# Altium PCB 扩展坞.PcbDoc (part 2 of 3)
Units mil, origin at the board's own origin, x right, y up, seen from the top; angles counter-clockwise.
Board outline 3543.31 x 1968.5 mil, 4 copper layers (Top Layer 1, Layer1, Layer2, Bottom Layer 1), stack 62.337 mil thick; 191 components, 182 nets, 737 pads, 256 vias.
Unrouted connection lines stored in the file: 242.
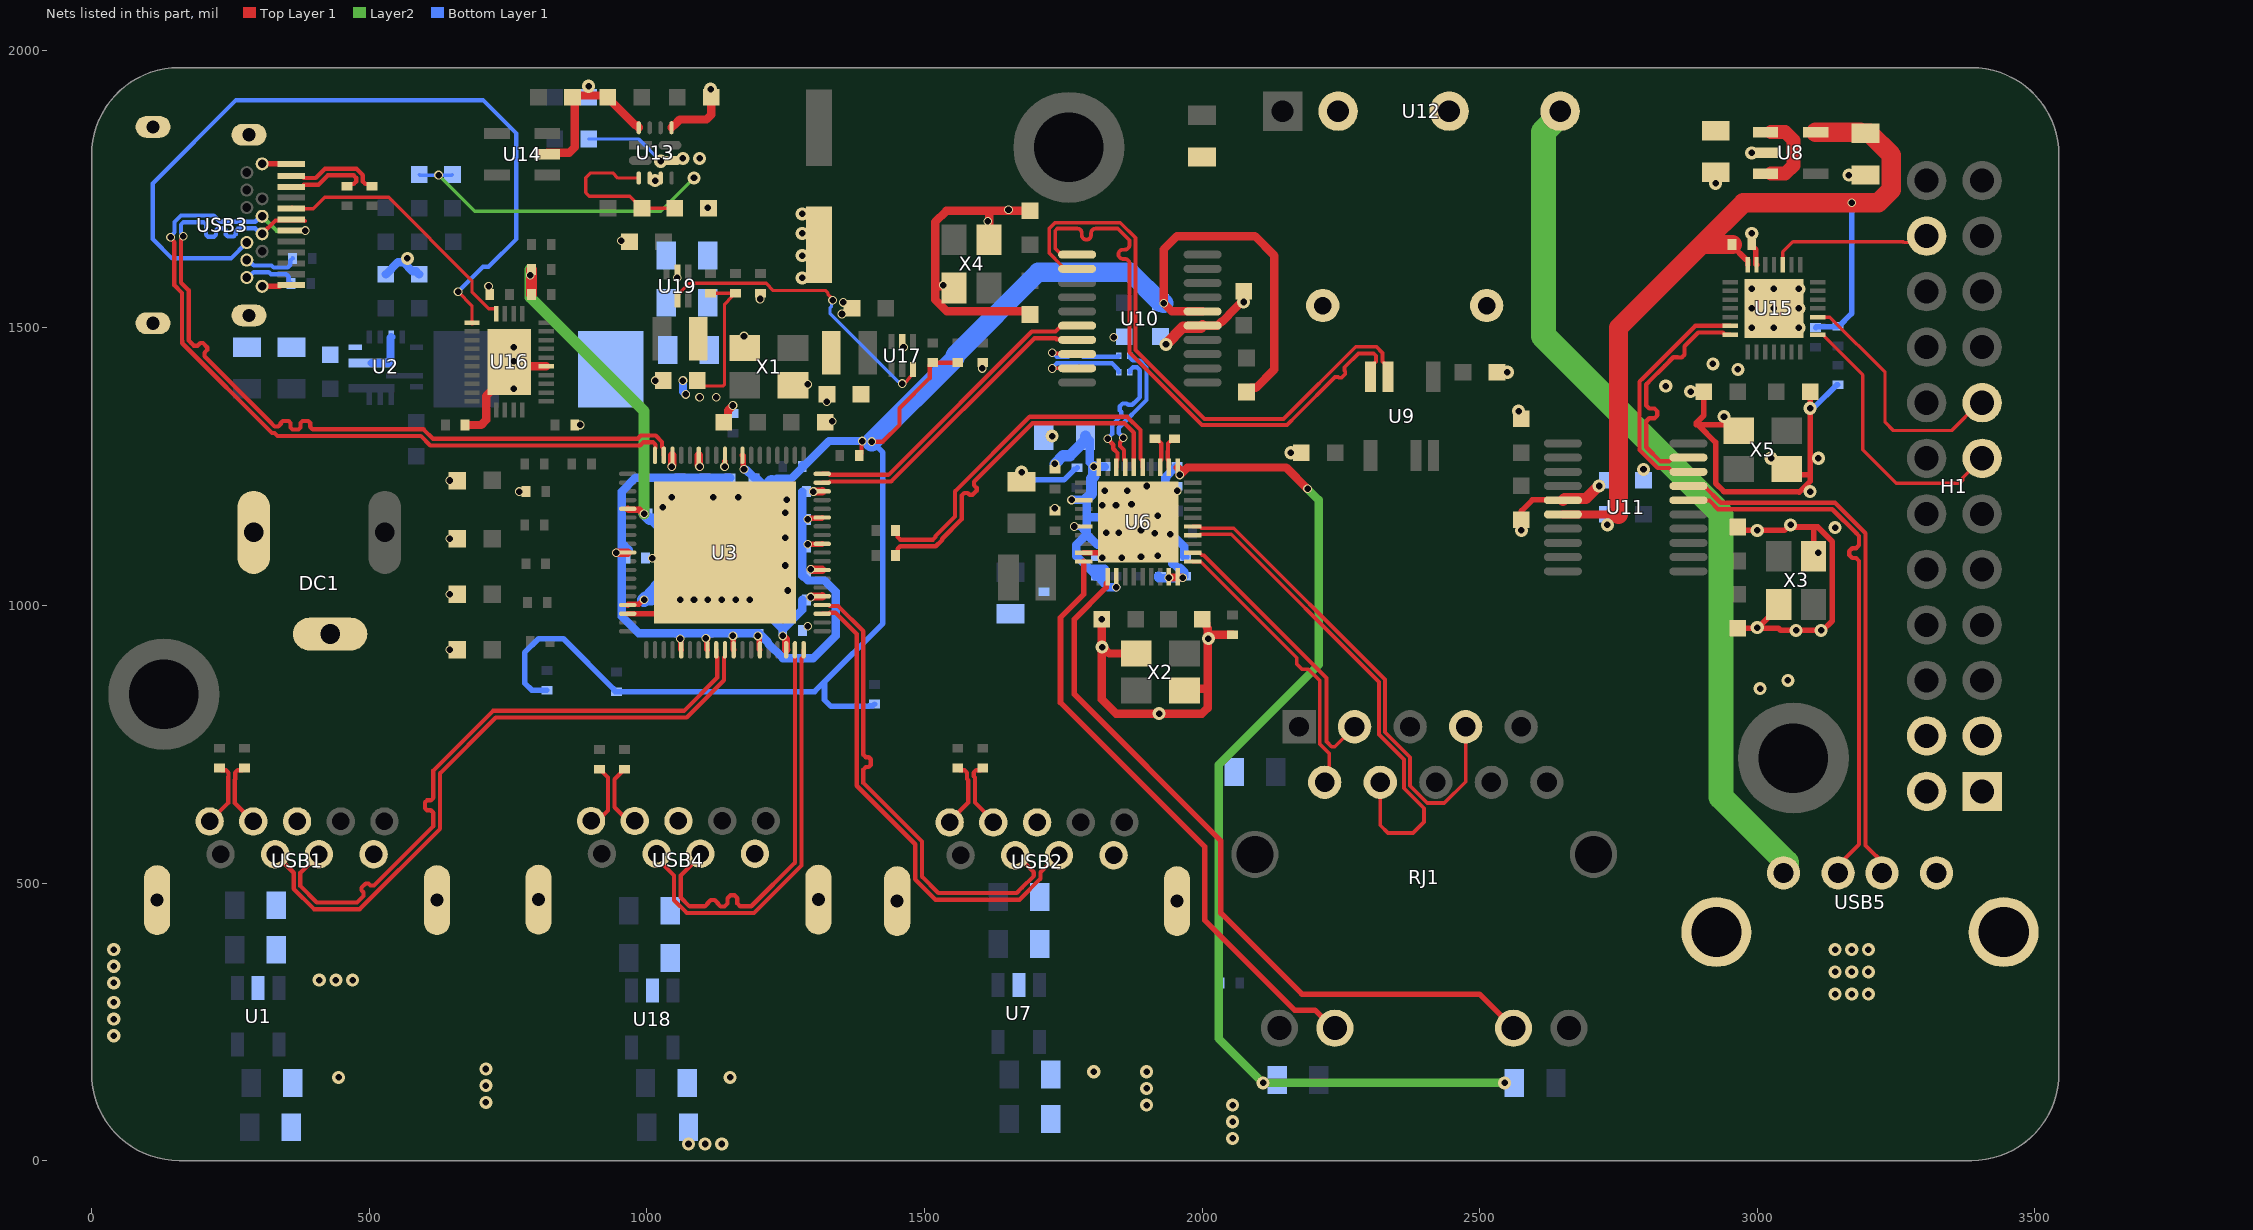
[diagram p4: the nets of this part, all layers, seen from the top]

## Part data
* *1 *2: "铜柱孔"
C1 C2 C3 C4 C5 C6 C7 C8 C9 C10 C11 C12 C13 C14 C15 C16 C17 C18 C19 C20 C21 C22 C23 C24 C25 C26 C27 C28 C29 C30 C31 C32 C33 C34 C35 C36 C38 C39 C40 C41 C42 C43 C44 C45 C46 C47 C48 C49 C50 C51 C52 C53 C54 C55 C56 C57 C58 C59 C60 C61 C62 C63 C64 C65 C66 C67 C68 C69 C70 C71 C72 C73 C74 C75 C76 C77 C78 C79 C80 C81 C82 C83 C84 C85 C87 C88 C89 C90 C91 C92 C93 C94 C95 C96 C97 C98 C99 C100 C101: library part C, "无极性贴片电容"
C37: "容值:220uF;精度:±20%;额定电压:25V;纹波电流:2.9A@100kHz;等效串联电阻(ESR):28mΩ@100kHz;类型:聚合物;", Equivalent Series Resistance(ESR)=28mΩ@100kHz, JLCPCB Part Class="Extended Part", LCSC Part Name="220uF ±20% 25V", Manufacturer=JIERR(捷而瑞), ManufacturerPart=MA25V220M6X8, Operating Temperature=-55℃~+105℃, Ripple Current=2.9A@100kHz, Tolerance=±20%, Voltage Rating=25V
C86: "容值:2.2nF;精度:±20%;工作电压(AC):300V;防护等级:Y2;", JLCPCB Part Class="Extended Part", LCSC Part Name="2.2nF ±20% 300V 等级:Y2", Manufacturer=QNR(勤宏科技), ManufacturerPart=Q222M060110FQ55250L7579, Operating Temperature=-40℃~+125℃, Ratings=Y2, Tolerance=±20%, Voltage(AC)=300V
DC1: "连接器类型:DC电源插座;安装方式:弯插;触点内径:2mm;触点外径:6.4mm;额定电流:3A;额定电压:30V;工作温度:-20℃~+70℃;", Current Rating=3A, JLCPCB Part Class="Extended Part", LCSC Part Name="DC电源插座 内径:2mm 外径:6.4mm", Manufacturer=XUNPU(讯普), ManufacturerPart=DC-005-A200, Operating Temperature=-20℃~+70℃, Voltage Rating (Max)=30V
H1: "插针结构:2x12P;间距:2.54mm;行距:2.54mm;圆针/方针:方针;排数:双排;总PIN位数:24P;额定电流:3A;额定电压:250V;配合针长度:-;塑高:2.5mm;端接针长度:-;触头材质:黄铜;触头镀层:金;工作温度:-40℃~+105℃;颜色:黑色;", Color=黑色, Current Rating=3A, JLCPCB Part Class="Extended Part", LCSC Part Name="2x12P 间距:2.54mm 方针", Manufacturer="XKB Connection(中国星坤)", ManufacturerPart=X6521WR-2x12H-C60D30, Operating Temperature=-40℃~+105℃, Voltage Rating (Max)=250V
L2: "合金电感 一体成型电感 大电流", JLCPCB Part Class="Extended Part", LCSC Part Name="3.3μH ±20% 9A", Manufacturer=JIERR(捷而瑞), ManufacturerPart=PCR0630-3R3-M
L3: "电感值:2.2uH;精度:±20%;额定电流:3A;饱和电流(Isat):3.8A;类型:磁胶屏蔽电感;", Current - Saturation(Isat)=3.8A, Current Rating=3A, DC Resistance(DCR)=55mΩ, JLCPCB Part Class="Extended Part", LCSC Part Name="2.2uH ±20% 3.8A", Manufacturer=SXN(顺翔诺), ManufacturerPart=SMMS252012-2R2M, Tolerance=±20%
LED1 LED2 LED3 LED4: "灯头类型:1.6mmx0.8mm方形灯头;发光颜色:翠绿色;正向压降(Vf):2.6V~2.9V;功率:90mW;正向电流:30mA;波长:520nm~525nm;二极管配置:独立二极管;透镜颜色:-;色温:-;发光强度:230mcd;发光角度:120°;载带方式:-;工作温度:-40℃~+85℃;", Color Temperature=-, Forward Current=30mA, Illumination Color=翠绿色, JLCPCB Part Class="Extended Part", LCSC Part Name=0603翠绿, Manufacturer=TUOZHAN(拓展光电), ManufacturerPart=F.0603.00025/P2-0603G1TS2-06T-002, Operating Temperature=-40℃~+85℃, Power(Watts)=90mW, Voltage - Forward(Vf)=2.6V~2.9V
R1 R2 R3 R4 R5 R6 R7 R8 R9 R10 R11 R12 R13 R14 R15 R16 R17 R18 R19 R20 R21 R22 R23 R24 R25 R26 R27 R28 R29 R30 R31 R32 R33 R34 R35 R36 R37 R38 R39 R40 R41 R42 R43 R44 R45 R46 R47 R48 R49: library part R, "贴片电阻"
RJ1: "连接器类型:RJ45插座;安装方式:弯插;端口数量:1;LED:带LED;屏蔽:有屏蔽;等级:-;触头材质:磷青铜;触头镀层:金;工作温度:0℃~+70℃;", JLCPCB Part Class="Extended Part", LCSC Part Name="弯插 带LED", Manufacturer=HANRUN(汉仁), ManufacturerPart=HR911130A, Operating Temperature=0℃~+70℃, Ratings=-
U1 U7 U18: "类型:负载开关;通道数:1;输入控制逻辑:高电平有效;工作电压:2.5V~5.5V;最大连续电流:2A;导通电阻:60mΩ;", JLCPCB Part Class="Extended Part", LCSC Part Name=低损耗功率分配开关, Manufacturer=Silergy(矽力杰), ManufacturerPart=SY6288CAAC, Maximum Continuous Current=2A, Operating Temperature	-=-40℃~+85℃, Voltage - Supply=2.5V~5.5V
U2: "功能类型:降压型;输出类型:可调;输入电压:4.5V~28V;输出电压:600mV~13V;输出电流(最大值):6A;", Input Voltage=4.5V~28V, JLCPCB Part Class="Extended Part", LCSC Part Name=TPS56637RPAR, Manufacturer=TI(德州仪器), Operating Temperature=-40℃~+150℃@(TJ), Output Current (Max)=6A, Output Voltage=600mV~13V, Switching Frequency=500kHz
U3: "VL822是一款USB 3.1 Gen2集线器控制器，具有高度集成的专用应用设计。VL822有1个上游端口和4个/2个下游端口，所有端口均支持10Gbps的USB 3.1 Gen2操作。下游端口可支持超速+（10Gbps）、超速（5Gbps）、高速（480Mbps）、全速（12Mbps）和低速（1.5Mbps）设备的任意组合", JLCPCB Part Class="Extended Part", LCSC Part Name="USB 3.1 Gen 2 集线器控制器", Manufacturer="VIA Labs(威锋电子)", ManufacturerPart=VL822-Q7, Voltage - Supply=0.95V~1.05V；3V~3.6V
U4 U5: "小型化一体成型T-CORE，小体积，扁线工艺，感值小", JLCPCB Part Class="Extended Part", LCSC Part Name="1uH ±20% 5.6A", Manufacturer=cjiang(长江微电), ManufacturerPart=FTC252012S1R0MBCA
U6: "类型:-;端口数量:1;MAC接口:-;", JLCPCB Part Class="Extended Part", LCSC Part Name="集成10/100/1000M以太网控制器用于USB 3.0应用", Manufacturer=REALTEK(瑞昱), ManufacturerPart=RTL8153B-VB-CG, Operating Temperature=0℃~+70℃, Power=-, Voltage - Supply=3.3V；1V；5V
U8: "输出极性:正极;工作电压:5.5V;输出电压:3.3V;输出电流:500mA;电源纹波抑制比(PSRR):50dB@(10kHz);输出类型:固定;", JLCPCB Part Class="Extended Part", LCSC Part Name="3.3V 500mA 5.5V", Manufacturer=RICHTEK(立锜), ManufacturerPart=RT9013-33GB, Operating Temperature=-40℃~+125℃@(Tj), Output Current=500mA, Output Voltage=3.3V, Power Supply Rejection Ratio (PSRR)=50dB@(10kHz), standby current=25uA, Voltage - Supply=5.5V, Voltage Dropout=400mV@(500mA)
U9: "线路数:4;电感@频率:120uH@100kHz;阻抗@频率:-;直流电阻(DCR):1.2Ω;", Current Rating=720mA, DC Resistance(DCR)=1.2Ω, Impedance @ Frequency=-, Inductance @ Frequency=120uH@100kHz, JLCPCB Part Class="Extended Part", LCSC Part Name="1G 30W 分离式变压器", Manufacturer=CND-tek(磁联达), ManufacturerPart=GA021G00, Operating Temperature=-40℃~+85℃, Voltage Withstand=1.5kV
U10 U11: "是高速USB信号隔离和传输距离延长控制芯片，支持电容耦合或者网络变压器耦合，不但实现了对USB信号的隔离，同时实现了对USB信号的实时中转和传输距离延长。此外，芯片自身带有USBHUB功能，上行端口支持USB2.0高速，下行端口支持USB2.0高速480Mbps、全速12Mbps和低速1.5Mbps。可以用于高速USB信号隔离、隔离HUB、延长HUB等。", Isolation Voltage(Vrms)=-, JLCPCB Part Class="Extended Part", LCSC Part Name=CH318T, Manufacturer=WCH(南京沁恒), Operating Temperature=-40℃~+85℃, Voltage - Supply=3.3V
U12: "DC-DC隔离电源模块:输入5V(4.5V~5.5V)@@输出5V 400mA 2W@@输出短路保护@@输入输出隔离耐压1.5KV@@SIP7", Capacitive Load(Max)=2400uF, Isolation Voltage(Vrms)=1.5kV, JLCPCB Part Class="Extended Part", LCSC Part Name="4.5V~5.5V 5V 400mA 2W", Manufacturer=EVISUN(易成), ManufacturerPart=B0505S-2WR3, Operating Temperature=-40℃~+105℃, Output Current(Max)=400mA, Output Power=2W, Output Voltage=5V, Quiescent Supply Current=8mA, Voltage - Supply=4.5V~5.5V, Voltage Regulation=非稳压型
U13: "TPS2121 支持无缝切换的 2.7V 至 22V、56mΩ、4.5A 电源多路复用器", JLCPCB Part Class="Extended Part", LCSC Part Name=TPS2121RUXR, Manufacturer=TI(德州仪器)
U14: "类型:高侧开关;通道数:1;输入控制逻辑:高电平有效;工作电压:2.4V~5.5V;最大连续电流:2A;导通电阻:80mΩ;", JLCPCB Part Class="Extended Part", LCSC Part Name=低损耗功率分配开关, Manufacturer=Silergy(矽力杰), ManufacturerPart=SY6280AAC, Maximum Continuous Current=2A, Operating Temperature	-=-40℃~+125℃, Voltage - Supply=2.4V~5.5V
U15: "应用功能:USB转UART；USB转SPI；USB转SWD；USB转I2C；USB转JTAG;USB协议版本:USB 2.0;通道数:2;数据速率:480Mbps;", Current - Supply=38mA, JLCPCB Part Class="Extended Part", LCSC Part Name="高速 USB 转换芯片", Manufacturer=WCH(南京沁恒), ManufacturerPart=CH347F, Operating Temperature=-, Quiescent Supply Current=260uA, Voltage - Supply=3V~3.6V
U16: "特性：USB Type-C数据开关，带适用于USB 3.1 Gen2 (10 Gbps)的CC功能。 4:2 10Gbps USB Type-C数据开关。 支持高达10Gbps。应用：线缆+设备应用", Current - Supply=1.2mA, JLCPCB Part Class="Extended Part", LCSC Part Name="支持CC功能的USB 3.1 Gen2 USB Type-C数据开关", Manufacturer="VIA Labs(威锋电子)", ManufacturerPart=VL162, Operating Temperature=-45℃~+85℃, Quiescent Supply Current=0.5mA, Voltage - Supply=4.5V~5.5V
U17 U19: "功能类型:降压型;工作电压:2.5V~5.5V;输出电压:600mV~5.5V;输出电流:3A;输出类型:可调;", Frequency - Switching=2MHz, JLCPCB Part Class="Extended Part", LCSC Part Name="降压型 3A 2.5V~5.5V", Manufacturer=ETA(钰泰), ManufacturerPart=ETA3512FSG, Operating Temperature=-40℃~+85℃@(TA), Output Current=3A, Output Voltage=600mV~5.5V, Quiescent Current=50uA, Voltage - Supply=2.5V~5.5V
USB1 USB2 USB4: "连接器类型:Type-A;协议标准:USB 3.0;公母:母;安装方式:弯插;触点数量:9P;端口数量:1;额定电流 - 电源:1.5A;工作温度:-25℃~+70℃;", Current Rating-Power=1.5A, Detection color=蓝色, JLCPCB Part Class="Extended Part", LCSC Part Name="Type-A 母 弯插 USB3.0 AF90度 直脚蓝胶卷边 吸塑盒", Manufacturer=HC(虹成电子), ManufacturerPart=HC-USB3.0-L168-ZJ, Operating Temperature=-25℃~+70℃, Voltage Rating=30V
USB3: "连接器类型:Type-C;协议标准:USB 3.1;公母:母;安装方式:卧贴;触点数量:24P;端口数量:1;额定电流 - 电源:3A;工作温度:-40℃~+85℃;", Current Rating-Power=3A, Detection color=黑色, JLCPCB Part Class="Extended Part", LCSC Part Name=24P卧贴母座, Manufacturer="SHOU HAN(首韩)", ManufacturerPart="TYPE-C 24P QCHT", Operating Temperature=-40℃~+85℃, Voltage Rating=30V
USB5: "连接器类型:Type-A;协议标准:USB 2.0;公母:母;安装方式:弯插;触点数量:4P;端口数量:1;额定电流 - 电源:1.5A;工作温度:-25℃~+85℃;", Current Rating-Power=1.5A, Detection color=白色, JLCPCB Part Class="Extended Part", LCSC Part Name="Type-A 母 弯插", Manufacturer="SHOU HAN(首韩)", ManufacturerPart="AF 90° WJDG", Operating Temperature=-25℃~+85℃, Voltage Rating=30V
X1 X2: "晶振类型:贴片晶振;频率:25MHz;常温频差:±10ppm;负载电容:12pF;频率稳定度:±20ppm;", Equivalent Series Resistance(ESR)=50Ω, Frequency Stability=±20ppm, JLCPCB Part Class="Basic Part", LCSC Part Name="YSX321SL 25MHZ 4P 3225 12PF ±10PPM -40~85℃ (±20PPM)", Load Capacitance=12pF, Manufacturer=YXC(扬兴晶振), ManufacturerPart=X322525MOB4SI, Normal temperature Frequency Tolerance=±10ppm, Operating Temperature=-40℃~+85℃
X3 X4: "晶振类型:贴片晶振;频率:20MHz;常温频差:±10ppm;负载电容:20pF;频率稳定度:±20ppm;", Equivalent Series Resistance(ESR)=50Ω, Frequency Stability=±20ppm, JLCPCB Part Class="Extended Part", LCSC Part Name="YSX321SL 20MHZ 4P 3225 20PF ±10PPM -40~85℃ (±20PPM)", Load Capacitance=20pF, Manufacturer=YXC(扬兴晶振), ManufacturerPart=X322520MSB4SI, Normal temperature Frequency Tolerance=±10ppm, Operating Temperature=-40℃~+85℃
X5: "晶振类型:贴片晶振;频率:8MHz;常温频差:±10ppm;负载电容:12pF;频率稳定度:±20ppm;", Equivalent Series Resistance(ESR)=180Ω, Frequency Stability=±20ppm, JLCPCB Part Class="Extended Part", LCSC Part Name="YSX321SL 8MHZ 4P 3225 12PF ±10PPM -40~85℃ (±20PPM)", Load Capacitance=12pF, Manufacturer=YXC(扬兴晶振), ManufacturerPart=XL2EL89COI-111YLC-8M, Normal temperature Frequency Tolerance=±10ppm, Operating Temperature=-40℃~+85℃

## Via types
v1: diameter 15.75, hole 11.81, Top Layer 1 to Bottom Layer 1, tented both sides, 127 vias
v2: diameter 23.62, hole 11.81, Top Layer 1 to Bottom Layer 1, tented both sides, 118 vias
v3: diameter 15.75, hole 11.81, Top Layer 1 to Bottom Layer 1, 10 vias
v4: diameter 23.62, hole 11.81, Top Layer 1 to Bottom Layer 1, 1 vias

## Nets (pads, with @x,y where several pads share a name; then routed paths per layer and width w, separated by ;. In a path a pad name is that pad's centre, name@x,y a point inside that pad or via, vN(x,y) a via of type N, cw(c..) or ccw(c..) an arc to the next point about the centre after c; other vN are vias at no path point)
1V05_SYS: C1.2 C2.2 C5.2 C6.2 C7.2 C8.2 C10.2 C11.2 C12.2 C13.2 C75.2 C79.1 C80.2 C81.2 R9.1 U3.5 U3.8 U3.11 U3.14 U3.27 U3.30 U3.33 U3.36 U3.48 U3.51 U3.54 U3.67 U5.2 | length 1741.8
  Top Layer 1 w6: C75.2@1090.59,1405 1100.59,1395 1136.49,1395 1140,1398.51 1140,1542.28 1153.16,1555.44 1153.16,1557.41 C79.1@1158.03,1562.28 ; R9.1@1115,1562.28 C79.1@1158.03,1562.28 ; C79.1@1160,1562.28 C79.1@1158.03,1562.28
  Top Layer 1 w10: v1(1060,940) 1060,938.34 1061,937.34 1061,921 U3.5@1062,920 ; v1(1106.38,940.98) 1107.48,939.88 1107.48,936.72 1108.14,936.06 1108.14,921.06 U3.8@1109.2,920 ; v1(1140,1250) 1140.35,1250.35 U3.48@1140.35,1259.65 ; v1(1155,945) 1155.7,944.3 1155.7,920.7 U3.11@1156.4,920 ; v1(1200,945) 1200,943.44 1202.64,940.81 1202.64,921.06 U3.14@1203.7,920 ; v1(1290,1110) 1290.45,1110.45 1315.45,1110.45 U3.30@1315.9,1110.9 ; v1(1290,1155) 1291.56,1155 1293.69,1157.14 1314.84,1157.14 U3.33@1315.9,1158.2
  Top Layer 1 w15: v1(945,1095) 945.1,1095.1 965.4,1095.1 U3.67@965.5,1095.2 ; v1(1045,1250) 1045.14,1250.14 1045.14,1251.4 1045.94,1252.19 1045.94,1270.14 U3.54@1046.2,1270.4 ; U3.51@1093.5,1270.4 1093.76,1270.14 1093.76,1252.19 1094.86,1251.1 1094.86,1250.14 v1(1095,1250) ; v1(1295,1065) 1295.14,1064.86 1296.9,1064.86 1297.69,1064.06 1315.54,1064.06 U3.27@1315.9,1063.7 ; v1(1300,1205) 1300.14,1205.14 1315.64,1205.14 U3.36@1315.9,1205.4
  Bottom Layer 1 w15: 967.29,1100 955,1112.28 ; v1(1065,1405) 1065.14,1404.86 1065.14,1385.06 1070,1380.2 v1(1070,1380) ; C8.2@1150,1230 C5.2@1105,1230 C10.2@1060,1230 980,1230 955,1205 955,1112.28 ; C1.2@1280,1205 1280,1053.03 1280.37,1052.66 1282.34,1052.66 1290,1045 1320,1045 1340,1025 1340,945 1300,905 1245,905 1218.31,931.69 1218.31,933.66 1201.97,950 C11.2@1200,950 C12.2@1155,950 C13.2@1110,950 C6.2@1060,950 985,950 955,980 955,1112.28
  other v1: 1095,1375 1125,1375
3V3_PG: U17.6 U19.5 | length 564.4
  Top Layer 1 w6: U19.5@1055.01,1549.8 1055.01,1557.67 1062.03,1564.7 1062.03,1565.94 1075.9,1579.81 1083.1,1579.81 1083.28,1580 1214.9,1580 1227.89,1567.01 1321.99,1567.01 1326.23,1562.77 1326.23,1560.66 1334.5,1552.39 v1(1334.5,1549.75) ; v1(1460,1399.54) 1461.87,1401.41 1465.41,1401.41 1472.66,1408.66 1472.66,1409.9 1479.69,1416.93 U17.6@1479.69,1424.8 U17.6@1479.69,1432.67
  Bottom Layer 1 w6: v1(1334.5,1549.75) 1332.64,1547.89 1332.64,1538.52 1330,1535.88 1330,1525.29 1451.94,1403.34 1453.56,1403.34 1457.36,1399.54 v1(1460,1399.54)
3V3_SYS: C3.2 C4.2 C24.2 C25.2 C56.2 C74.2 C78.1 C92.2 R7.1 R10.2 R11.2 R18.1 R26.1 R34.1 R35.1 R36.1 R37.1 R38.1 R39.1 R40.1 U3.17 U3.24 U3.46 U3.62 U3.73 U4.2 U10.16 | length 4944.3
  Top Layer 1 w7.74: R40.1@1382.72,1270 1386.47,1273.75 1386.47,1294.47 v1(1388,1296) ; C56.2@1385.59,1380 C56.2@1395.59,1370 ; v3(1405,1295) 1425,1295 1455,1325 1455,1355 1509.31,1409.31 1509.31,1433.28 1513.32,1437.28 R7.1@1515,1437.28 C78.1@1560,1437.28
  Top Layer 1 w10: U3.73@965.5,1000.7 966.56,1001.76 985.21,1001.76 993.44,1010 v1(995,1010) ; U3.46@1172.2,1270.4 1173.26,1269.34 1173.26,1248.32 1175,1246.58 v1(1175,1245.03)
  Top Layer 1 w12: U3.62@965.5,1173.9 967.26,1172.14 986.85,1172.14 993.99,1165 v1(995,1165)
  Top Layer 1 w15: 1250.64,939.16 1250.64,920.26 U3.17@1250.9,920 ; v1(1295,1015) 1295.14,1015.14 1296.7,1015.14 1297.69,1016.14 1315.54,1016.14 U3.24@1315.9,1016.5 ; U10.16@2001.06,1529.4 2000.73,1529.73 1945.47,1529.73 1931.1,1544.1 v1(1930.9,1544.1) 1930.9,1640.9 1955,1665 2095,1665 2130,1630 2130,1425 2096.91,1391.91 2087.5,1391.91 R26.1@2080,1384.41
  Top Layer 1 w20: R11.2@792.29,1560 R10.2@792.29,1605
  Layer2 w20: 790,1605 v1(790,1595) 790,1555 995,1350 v1(995,1165)
  Bottom Layer 1 w10: R36.1@820,847.28 792.72,847.28 780,860 780,915 805,940 849.57,940 940.16,849.41 940.16,847.44 943.03,844.57 R18.1@945,844.57 1302.03,844.57 1320,862.54 ; v3(1405,1295) 1425,1275 1425,967.54 1320,862.54 ; R35.1@1410,822.28 1407.13,819.41 1400.58,819.41 1399.3,818.13 1331.87,818.13 1320,830 1320,862.54
  Bottom Layer 1 w15: v1(1175,1245.03) 1175.14,1244.88 1178.15,1244.88 C74.2@1193.03,1230 1196.97,1230 1220,1206.97 1225.2,1212.16 ; 1221.34,1015 1221.34,980.63 C25.2@1245,956.97 ; 1225.2,1219.6 1234.25,1228.65 1260.62,1228.65 1280,1248.03 1280,1251.97 1280.37,1252.34 1284.31,1252.34 1327.97,1296 v1(1388,1296) 1388.14,1295.86 1403.94,1295.86 1404.8,1295 v3(1405,1295) ; C25.2@1245,955 C25.2@1245,956.97 ; C4.2@1280,1010 1279.63,1009.63 1279.63,991.59 C25.2@1245,956.97
  Bottom Layer 1 w20: v1(995,1165) 1004.85,1155.15 1010.05,1155.15 1024.04,1141.16 1051.39,1141.16 1059.59,1149.36 1059.59,1149.59 1075,1165 1225.2,1165 ; 1065.43,1036.06 1077.72,1048.34 R37.1@1077.72,1090 ; 1150,1036.06 1157.72,1043.77 R38.1@1157.72,1095 R39.1@1157.72,1135
  Bottom Layer 1 w25: v1(995,1010) 997.29,1012.29 1007.29,1012.29 1007.29,1020.55 1018.34,1031.61 1018.34,1033.14 1032.99,1047.79 1053.7,1047.79 1065.43,1036.06 1150,1036.06 1200.28,1036.06 1221.34,1015
  Bottom Layer 1 w30: 1221.34,1015 1221.34,1178.29 1221.88,1178.83 1221.88,1208.47 1221.5,1208.47 ; 1225.2,1212.16 1225.2,1219.6
  Bottom Layer 1 w35: v3(1405,1295) 1555,1445 1555,1450 1705,1600 1870.59,1600 C92.2@1925,1545.59 1929.41,1545.59 v1(1930.9,1544.1)
  other v1: 1245,945
+5V: C14.2 C15.2 C16.2 L2.2 R1.1 R2.2 R48.2 U13.7 | length 718.7
  Layer2 w6: v1(625,1775) 690,1710 1025,1710 v2(1085,1770)
  Bottom Layer 1 w6: R2.2@590,1776.18 591.18,1775 v1(625,1775) 648.82,1775 R1.1@650,1776.18 ; R48.2@895.59,1840 985,1840 v2(1025,1800)
  other v2: 1065,1805 1095,1805
AC_P1C_SS_TX_N: C73.2 USB3.B2 | length 97
  Bottom Layer 1 w7.74: USB3.B2@279.58,1590.51 282.31,1590.51 292.06,1600.25 319.21,1600.25 322.96,1596.49 350.63,1596.49 355.16,1591.96 355.16,1584 C73.2@359.17,1579.99 ; C73.2@359.37,1580.2 C73.2@359.57,1580
AC_P1C_SS_TX_P: C72.2 USB3.B3 | length 99.7
  Bottom Layer 1 w7.74: USB3.B3@279.59,1621.99 282.32,1621.99 292.06,1612.25 324.18,1612.25 327.93,1608.49 353.34,1608.49 357.88,1613.03 357.88,1620.99 C72.2@361.88,1624.99 ; C72.2@362.08,1624.79 C72.2@362.29,1625
AC_SS1_TX_N: C31.1 USB3.A3 | length 154
  Top Layer 1 w7.74: USB3.A3@359.32,1753.9 378.51,1753.9 382.35,1757.74 408.72,1757.74 425.47,1774.48 471.97,1774.48 476.5,1769.95 476.5,1763.54 471.97,1759 464,1759 C31.1@460,1755
AC_SS1_TX_P: C30.1 USB3.A2 | length 173.9
  Top Layer 1 w7.74: USB3.A2@359.32,1773.59 378.51,1773.59 382.35,1769.74 403.75,1769.74 420.5,1786.48 476.94,1786.48 488.5,1774.92 488.5,1763.54 493.03,1759 501,1759 C30.1@505,1755
AC_SS2_RX_N: C39.2 U6.12 | length 59
  Top Layer 1 w7.74: U6.12@1940.12,1248.4 1940.12,1260.21 1938.24,1262.09 1938.24,1277.34 1938.5,1277.59 1938.5,1291.46 1943.03,1296 1946,1296 C39.2@1950,1300
AC_SS2_RX_P: C40.2 U6.13 | length 59
  Top Layer 1 w7.74: C40.2@1915,1300 1919,1296 1921.97,1296 1926.5,1291.46 1926.5,1282.57 1926.24,1282.31 1926.24,1262.09 1924.37,1260.21 U6.13@1924.37,1248.4
AC_SS2_TX_N: C36.2 U6.15 | length 651.3
  Top Layer 1 w7.74: C36.2@1447.71,1135 1451.72,1130.99 1451.72,1123.03 1456.25,1118.5 1515.47,1118.5 1520,1123.03 1520,1125 1555,1160 1555,1205.37 1689.63,1340 1860.03,1340 1860.22,1339.81 1865.06,1339.81 1888.94,1315.93 1888.94,1264.14 1892.87,1260.21 U6.15@1892.87,1248.4
AC_SS2_TX_P: C29.2 U6.16 | length 647.6
  Top Layer 1 w7.74: C29.2@1447.71,1090 1451.72,1094 1451.72,1101.96 1456.25,1106.5 1520.44,1106.5 1532,1118.06 1532,1120.03 1567,1155.03 1567,1183 1567,1198.08 1571.53,1202.62 1577.95,1202.62 1581.44,1199.12 1586.46,1199.12 1593.99,1206.64 1593.99,1211.66 1589.33,1216.32 1589.33,1222.73 1593.3,1226.7 1694.6,1328 1860.17,1328 1877.13,1311.04 U6.16@1877.13,1248.4
AC_SS3_TX_N: C34.1 USB2.8 | length 121.8
  Top Layer 1 w7.74: C34.1@1605,707.28 1601,703.28 1593.09,703.28 1588.56,698.75 1588.56,692.33 1590.92,689.97 1590.92,645.1 USB2.8@1624.29,611.73
AC_SS3_TX_P: C35.1 USB2.9 | length 121.9
  Top Layer 1 w7.74: USB2.9@1545.56,611.73 1578.92,645.09 1578.92,685 1576.56,687.36 1576.56,698.69 1571.97,703.28 1564,703.28 C35.1@1560,707.28
AC_SS4_TX_N: C27.1 USB4.8 | length 124
  Top Layer 1 w7.74: C27.1@960,705 958.03,705 954.03,701 954.03,699.03 941.74,686.74 941.74,636.46 966.47,611.73 USB4.8@978.23,611.73
AC_SS4_TX_P: C28.1 USB4.9 | length 120.2
  Top Layer 1 w7.74: USB4.9@899.49,611.73 911.25,611.73 930,630.48 930,690 920.97,699.03 920.97,701 916.97,705 C28.1@915,705
AC_TX1_N: C33.1 USB1.9 | length 122
  Top Layer 1 w7.74: USB1.9@212.52,610.87 245.89,644.23 245.89,691.19 246.5,691.8 246.5,698.75 241.97,703.28 234,703.28 C33.1@230,707.28
AC_TX1_P: C32.1 USB1.8 | length 122
  Top Layer 1 w7.74: C32.1@275,707.28 271,703.28 263.03,703.28 258.5,698.75 258.5,686.83 257.89,686.22 257.89,644.24 USB1.8@291.26,610.87
ACT: H1.13 U15.8 | length 508.6
  Top Layer 1 w6: U15.8@3108.74,1487.76 3118.58,1487.76 3119.52,1486.82 3119.52,1485.48 3190,1415 3190,1280 3250,1220 3365,1220 3370,1225 3370,1230 H1.13@3405,1265
AVD3V3: C9.2 C38.2 C46.2 C47.2 C48.2 C49.2 C71.2 R20.2 R22.1 R30.2 U6.11 U6.20 U6.23 U6.26 U6.33 U6.39 U6.40 | length 3139.1
  Top Layer 1 w15: v1(1940.38,1049.86) 1940.66,1050.14 1964.86,1050.14 v1(1965,1050) ; U6.11@1955.87,1248.4 1959.43,1244.84 1959.43,1235.58 1959.81,1235.2 v1(1959.81,1235) 1960.01,1235 1973.41,1248.4 2151.6,1248.4 v1(2190,1210)
  Layer2 w15: v1(2190,1210) 2210,1190 2210,892.92 2030,712.92 2030,220 v2(2110,140) v2(2545,140)
  Bottom Layer 1 w10: v1(1769.6,1142.12) 1770.7,1141.03 1779.29,1141.03 1785.48,1134.84 1789.41,1134.84 1792.29,1131.97 C48.2@1792.29,1130 C48.2@1792.29,1128.03
  Bottom Layer 1 w15: v1(1765,1190) 1765.14,1190.14 1790.14,1190.14 1792.29,1192.29 1792.29,1161.14 ; 1788.66,1075.08 1797.64,1066.1 1824.83,1066.1 1823.66,1064.92 1823.66,1039.65 1830.4,1032.91 v1@1837.51,1032.91 ; C71.2@1790,1305 1797.7,1297.3 1797.7,1257.5 ; C48.2@1792.29,1131.97 1792.29,1153.65 ; 1792.29,1159.02 1877.33,1159.02 1896.33,1178.02 1911.95,1193.64 ; v1(1805,1250) C38.2@1825,1250 ; C47.2@1807.66,1052.66 1811.6,1052.66 1822.95,1041.31 1822.95,1040.36 1830.77,1032.54 v1(1845.22,1032.54) ; C47.2@1807.66,1054.63 1773.66,1088.63 1773.66,1109.4 1792.29,1128.03 1811.66,1108.66 1886.98,1108.66 ; 1830.77,1032.16 1831,1032.4 1844.87,1032.4 v1@1845.36,1032.88 ; 1881.98,1154.37 1870.63,1143.02 1870.63,1126.98 1886.98,1110.63 1899.61,1110.63 ; 1899.98,1106.72 1901.92,1108.66 1938.04,1108.66 1948.66,1098.04 1948.66,1075.08 1960.16,1063.58 C46.2@1960.16,1052.29 ; C9.2@1921,1053.7 1921,1049.53 1921.53,1049 1952.66,1049 1953.66,1050 v1(1965,1050) ; 1935.37,1228.92 1933.66,1227.21 1933.66,1204.25 ; 1946.34,1075.08 1946.34,1100.35 ; 1946.83,1099.87 1946.83,1076.91 1955.39,1068.34 1960.19,1068.34 1967.66,1060.87 C46.2@1967.66,1051.91 ; C49.2@1955,1250 1953.03,1250 1933.66,1230.63 1933.66,1204.25 ; 1911.95,1193.64 1923.05,1193.64 ; 1911.94,1193.64 1923.05,1193.64 ; 1923.05,1193.64 1933.66,1204.25
  Bottom Layer 1 w20: v1(1735,1255) 1749.59,1269.59 1762.09,1269.59 1790,1297.5 C71.2@1790,1305 ; 1792.29,1192.29 1792.52,1192.29 1801.16,1200.93 1801.16,1228.24 1805,1232.08 v1(1805,1250)
CC1: U16.1 USB3.B5 | length 1438.4
  Top Layer 1 w6: v1(660,1565) 685.1,1539.9 U16.1@685.1,1509.34
  Top Layer 1 w10: U16.1@685.1,1509.34 U16.1@685.2,1509.24
  Bottom Layer 1 w7.74: USB3.B5@279.59,1653.49 251.09,1625 145,1625 110,1660 110,1760 260,1910 705,1910 765,1850 765,1660 715,1610 705,1610 v1(660,1565)
CC2: U16.28 USB3.A5 | length 483.6
  Top Layer 1 w6: USB3.A5@359.32,1714.52 399.53,1714.52 420,1735 535,1735 685,1585 685,1564.67 715.45,1534.22 727.56,1534.22 728.5,1533.29 U16.28@728.5,1525
  Top Layer 1 w7.74: USB3.A5@359.32,1714.52 USB3.A5@360.86,1716.07
CP2: R14.1 R15.2 U13.3 | length 301.2
  Top Layer 1 w6: U13.3@985.47,1769.73 947.95,1769.73 938.86,1778.81 898.81,1778.81 890,1770 890,1743.51 896.51,1737 969.18,1737 R14.1@991.18,1715 R15.2@1050,1715
CTS0: H1.22 U15.17 | length 295.1
  Top Layer 1 w6: U15.17@3045.74,1613.74 3045.74,1636.52 3064.22,1655 3262.63,1655 3264.16,1653.47 3293.47,1653.47 H1.22@3305,1665
DTR0: H1.15 U15.10 | length 454.3
  Top Layer 1 w6: U15.10@3108.74,1519.25 3130.75,1519.25 3230,1420 3230,1330 3245,1315 3350,1315 3400,1365 H1.15@3405,1365
DU2_N: U11.8 U15.27 | length 459.4
  Top Layer 1 w7.74: U11.8@2903.19,1240.59 U11.8@2876.06,1240.59 2847.9,1240.59 2841.1,1247.39 2820.64,1247.39 2788,1280.03 2788,1403 2795.03,1410.03 2881.47,1496.47 2888.5,1503.5 U15.27@2951.26,1503.5
DU2_P: U11.9 U15.28 | length 431.3
  Top Layer 1 w7.74: U11.9@2876.38,1266.5 U11.9@2876.06,1266.18 2847.9,1266.18 2841.1,1259.39 2825.61,1259.39 2800,1285 2800,1310 2800,1331.61 2805.32,1336.93 2814.68,1336.93 2820,1342.25 2820,1349.35 2814.68,1354.67 2805.32,1354.67 2800,1359.99 2800,1398.03 2801.1,1399.13 2804.97,1403 2833.49,1431.51 2848.77,1446.8 2856.29,1446.8 2856.44,1446.65 2863.97,1446.65 2868.98,1451.67 2868.98,1459.19 2868.84,1459.34 2868.84,1466.87 2875.99,1474.01 2893.47,1491.5 2937.68,1491.5 2941.42,1487.76 U15.28@2951.26,1487.76
DU_N: U11.6 USB5.2 | length 962.1
  Top Layer 1 w7.74: U11.6@2876.06,1189.41 2876.59,1188.88 2913.73,1188.88 2929.36,1173.26 3135.14,1173.26 3178.4,1130 3183.26,1125.14 3183.26,1108.39 3177.94,1103.07 3170.85,1103.07 3165.53,1097.75 3165.53,1090.65 3170.85,1085.33 3177.94,1085.33 3183.26,1080.01 3183.26,1075 3183.26,569.56 3150.63,536.93 USB5.2@3150.63,533.34
DU_P: U11.7 USB5.3 | length 965
  Top Layer 1 w7.74: U11.7@2876.06,1215 2904.22,1215 2934.22,1185 3140,1185 3195,1130 3195,567.72 USB5.3@3229.37,533.34
ETH1_D_N: R28.1 U6.17 | length 256.6
  Top Layer 1 w6.7: v1@1855.6,1301.96 v1(1858.04,1301.96)
  Top Layer 1 w7.74: v1(1858.04,1301.96) 1858.04,1299.79 1852.12,1293.86 1852.12,1287.01 1859.51,1279.62 1859.51,1262.09 1861.38,1260.21 U6.17@1861.38,1248.4
  Bottom Layer 1 w6.7: v1@1856.31,1303.69 v1(1858.04,1301.96)
  Bottom Layer 1 w7.74: v1(1858.04,1301.96) 1858.04,1302.47 1850.02,1310.49 1850.02,1320.05 1900,1370.03 1900,1428.6 1887.6,1441 1875.27,1441 1870.74,1445.53 1870.74,1448.95 R28.1@1869.68,1450
ETH1_D_P: R29.1 U6.18 | length 248.7
  Top Layer 1 w7.74: v1(1830,1300) 1830,1299.48 1840.12,1289.37 1840.12,1282.03 1847.51,1274.65 1847.51,1262.09 1845.63,1260.21 U6.18@1845.63,1248.4
  Bottom Layer 1 w7.74: v1(1830,1300) 1830,1300.52 1838.02,1308.54 1838.02,1325.02 1851.5,1338.5 1854.24,1341.24 1854.24,1348.76 1851.95,1351.05 1851.95,1358.58 1856.97,1363.59 1864.49,1363.59 1866.78,1361.31 1874.31,1361.31 1884,1371 1888,1375 1888,1423.63 1882.63,1429 1875.43,1429 1870.89,1424.47 1870.89,1421.05 R29.1@1869.84,1420
ETH_D_N: R28.2 U10.8 | length 177.1
  Top Layer 1 w6.7: v1(1730,1455) 1731.18,1453.82 U10.8@1773.82,1453.82
  Top Layer 1 w7.74: U10.8@1773.82,1453.82 U10.8@1775,1452.63
  Bottom Layer 1 w7.74: v1(1730,1455) 1731.5,1455 1738.54,1447.96 1755,1447.96 1758.87,1447.96 1763.4,1452.5 ; 1763.4,1452.54 1766.95,1456.09 1777.6,1456.09 1781.14,1452.54 ; 1781.14,1452.5 1785.68,1447.96 1790,1447.96 1848.95,1447.96 1850,1449.02 R28.2@1850,1450
ETH_D_P: R29.2 U10.9 | length 183.2
  Top Layer 1 w6.7: v1(1730,1426.69) 1730.18,1426.86 1774.82,1426.86 U10.9@1775,1427.04 U10.9@1778.51,1430.55
  Bottom Layer 1 w7.74: v1(1730,1426.69) 1730,1427.43 1738.54,1435.96 1837.61,1435.96 1849.11,1424.47 1849.11,1421.05 R29.2@1850.16,1420
GND: C1.1 C2.1 C3.1 C4.1 C5.1 C6.1 C7.1 C8.1 C9.1 C10.1 C11.1 C12.1 C13.1 C14.1 C15.1 C16.1 C19.2 C20.2 C21.2 C22.2 C23.1 C24.1 C25.1 C26.1 C37.2 C38.1 C41.1 C42.2 C43.2 C44.1 C45.1 C46.1 C47.1 C48.1 C49.1 C50.1 C51.1 C52.1 C53.1 C54.1 C55.1 C56.1 C57.1 C60.2 C63.1 C65.1 C67.2 C68.1 C69.1 C70.1 C71.1 C74.1 C75.1 C76.1 C77.1 C80.1 C81.1 C82.1 C83.1 C84.1 C85.1 C86.1 C92.1 C93.1 C94.1 C95.1 C96.1 C97.1 C98.1 C99.1 C100.1 C101.1 DC1.2 DC1.3 LED1.1 LED2.1 LED3.1 LED4.1 R3.1 R5.1 R6.2 R8.2 R13.1 R15.1 R16.1 R17.1 R19.1 R21.1 R25.2 R27.2 R33.2 R43.2 R49.1 U1.2 U2.3 U2.9 U2.10 U3.74 U3.77 U6.29 U6.41 U7.2 U10.15 U12.2 U13.4 U13.5 U13.9 U13.12 U14.2 U16.19 U16.29 U17.2 U18.2 U19.2 USB1.4 USB1.7 USB1.10 USB1.11 USB2.4 USB2.7 USB2.10 USB2.11 USB3.25 USB3.A1 USB3.A12 USB3.B1 USB3.B12 USB4.4 USB4.7 USB4.10 USB4.11 X1.2 X1.4 X2.2 X2.4 X4.2 X4.4 | length 3162.7
  Top Layer 1 w10: USB3.B1@307.14,1574.77 338.15,1574.77 340.12,1576.74 USB3.A12@359.32,1576.74 ; USB3.B12@307.15,1795.24 307.34,1795.04 359.12,1795.04 USB3.A1@359.32,1794.85 ; U3.74@965.5,985 U3.77@1030.5,985 ; U6.29@1786.6,1094.88 1829.88,1094.88 U6.41@1885,1150
  Top Layer 1 w15: R13.1@672.72,1325 701.75,1325 710.54,1333.79 710.54,1377.1 752.13,1418.7 U16.29@752.13,1438.38 760,1430.51 U16.19@819.06,1430.51 ; U14.2@820.42,1815 860,1815 870,1825 870,1917.88 869.53,1918.35 893.35,1918.35 895,1920 ; v2(895,1935) 895,1920 ; U13.12@985.47,1860.27 985.47,1861.02 981.91,1864.59 979.82,1864.59 C26.1@929.41,1915 926.06,1918.35 896.65,1918.35 895,1920 ; U3.77@1030.5,985 U3.77@1140.7,1095.2 ; U13.9@1044.53,1860.27 1044.53,1861.02 1048.09,1864.59 1048.84,1864.59 1059.26,1875 1107.39,1875 1116.18,1883.79 R16.1@1116.18,1915 ; C23.1@1138.82,1330 1146.32,1337.5 1146.32,1351.12 1155,1359.8 v1(1155,1360) ; X4.2@1553.51,1571.7 1550.2,1575 1519.37,1575 ; X4.4@1616.49,1658.31 1616.49,1708.76 1614.67,1710.59 ; R25.2@1690,1523.82 1683.82,1530 1540,1530 1519.37,1550.63 1519.37,1575 ; C67.2@1690,1710.59 1614.67,1710.59 ; v2(1819.41,975) 1819.41,830.59 1845,805 2000,805 2010,815 2010,850 ; v2(1820,925) 1821.23,925 1832.77,913.47 X2.4@1881.69,913.47 ; X2.2@1968.31,846.53 1971.78,850 2010,850 ; C41.1@2000.59,975 2008.09,967.5 2008.09,960.62 2010,958.71 v2@2010,940 ; U10.15@2001.06,1503.81 2027.52,1503.81 2034.44,1510.73 2035.92,1510.73 2048.5,1523.32 2048.5,1524.17 2069.09,1544.76 2073.12,1544.76 v2(2074.77,1546.41) ; R21.1@2055,947.28 2020.69,947.28 2013.69,940.28 v2(2011.35,940.28) 2010,938.92 2010,850 ; 1519.37,1575 1519.37,1690.63 1539.33,1710.59 1614.67,1710.59
  Top Layer 1 w20: v2(1935,1470) 1965.98,1500.98 1998.23,1500.98 U10.15@2001.06,1503.81
  Bottom Layer 1 w10: v2(1675,1240) 1678.69,1240 1692.69,1226 1751.32,1226 1770.16,1244.84 1772.13,1244.84 C55.1@1775,1247.72
  Bottom Layer 1 w15: U2.9@504.41,1436.7 537.87,1436.7 538.25,1437.07 538.25,1481.94 U2.3@539.85,1483.55 ; R5.1@530,1596.18 551.91,1618.09 v2@561.91,1618.09 ; v2(568.81,1625) v2@561.91,1618.09 ; R3.1@590,1596.18 584.49,1601.69 578.31,1601.69 v2@561.91,1618.09 ; v1(1029,1176.88) 1029.14,1176.74 1029.14,1175.55 1037.72,1166.97 C24.1@1037.72,1165 ; C3.1@1042.72,1015 1042.72,1013.03 1043.09,1012.66 v1@1057.14,1012.66 ; v1(1045,1195) 1045.14,1194.86 1059.72,1194.86 C10.1@1060,1194.57 ; C6.1@1060,985.43 v1(1060,1010) ; C5.1@1105,1194.57 1105.29,1194.86 1119.86,1194.86 v1(1120,1195) ; C13.1@1110,985.43 v1(1110,1010) ; C8.1@1150,1194.57 1150.29,1194.86 1164.86,1194.86 v1(1165,1195) 1165.2,1195 1165.63,1194.57 C74.1@1195,1194.57 ; C12.1@1155,985.43 1156.97,985.43 1157.34,985.8 1157.34,1007.14 1160,1009.8 v1(1160,1010) ; v1(1185,1010) 1185.14,1009.86 1185.14,998.32 1198.03,985.43 C11.1@1200,985.43 ; C70.1@1887.34,1087.72 C9.1@1922.66,1087.72 ; v1(1920,1089.28) 1923.43,1089.28 C9.1@1925,1087.72 ; v1(1942.41,1128.38) 1945.18,1128.38 1967.66,1105.91 1967.66,1088.09 1968.03,1087.72 C46.1@1970,1087.72
  other v1: 1289.74,962.57 1085,1010 1135,1010 1254,1026.88 1249,1071.88 1010,1085 1819.98,1086.13 1854.98,1086.13 1890,1087.72 1249,1121.88 1915,1130 1827.7,1131.13 1849.98,1131.13 1890,1135 1919.98,1161.13 1249,1166.88 1735,1175 1820,1180 1845,1180 1872.95,1182.05 1252.07,1190 1824.98,1206.13 1864.98,1206.13 1954.98,1206.13 1900,1215 1334,1331.88 1324,1366.88 1289.44,1398.04 1015,1405 1604,1426.88 1462.3,1465.12 1841.07,1482.98 1175,1485 1351.45,1524.87 1353.81,1545.6 1204,1551.88 715,1575 1533.78,1576.88 1055,1590 954,1656.88 1614,1691.88 1651.33,1712.47
  other v2: 1075,30 1105,30 1135,30 2055,40 2055,70 1900,100 2055,100 710,105 1900,130 710,135 445,150 1150,150 1805,160 1900,160 710,165 40,225 40,255 40,285 40,320 410,325 440,325 470,325 40,350 40,380 1922.5,805 2160,1275 1730,1305 1280,1590 1280,1630 1280,1670 1280,1705 1109.77,1716.41 1015,1765 1115,1930
  other v3: 645,920 645,1020 645,1120 770,1205 645,1225 880,1325 760,1390 760,1440 760,1465
GND_ISO: C58.1 C59.1 C61.1 C62.2 C64.1 C66.2 C86.2 C87.1 C88.2 C89.2 C90.1 C91.1 H1.1 H1.2 H1.3 H1.4 R23.2 R24.2 U8.2 U11.15 U12.4 U15.20 U15.29 USB5.4 USB5.5 X3.2 X3.4 X5.2 X5.4 | length 1598.9
  Top Layer 1 w10: v2(2575,1135) C64.1@2575,1154.41 2575,1170 2595,1190 2649.41,1190 U11.15@2650,1189.41 ; C88.2@2903.82,1385 2903.82,1342.5 2890,1328.69 2890,1325 2893.69,1325 ; C66.2@2965,958.82 3000,958.82 3038.19,958.82 3042.01,955 3117.72,955 3135,972.28 3135,1115 3108.82,1141.18 3100,1141.18 ; R24.2@2965,1141.18 2971.18,1135 3048.75,1135 3054.93,1141.18 3100,1141.18 ; X5.2@2966.69,1314.45 2956.15,1325 2893.69,1325 ; v2(2990,1670) C90.1@2990,1650 2990,1648.03 2997.44,1640.59 2997.44,1614.8 U15.20@2998.5,1613.74 ; v2(3000,960) 3001.73,960 3038.51,996.77 X3.4@3038.51,1001.7 ; X5.4@3053.31,1245.55 3063.85,1235 3095.59,1235 ; C87.1@3095.59,1385 3095.59,1235 ; X3.2@3101.49,1088.3 3101.49,1139.69 3100,1141.18 ; 2893.69,1325 2925,1293.69 2925,1220 2940,1205 3075,1205 3075.86,1204.14 3095.59,1223.87 3095.59,1235
  Top Layer 1 w20: U11.15@2650,1189.41 2652.83,1192.24 2691.26,1192.24 2714.02,1215 v2(2715,1215)
  Bottom Layer 1 w10: v2(3095,1355) 3097.61,1357.61 3103.35,1357.61 3143.03,1397.29 C89.2@3145,1397.29
  other v2: 3140,300 3170,300 3200,300 3140,340 3170,340 3200,340 3140,380 3170,380 3200,380 3005,850 3055,865 3070,955 3115,955 3110,1095 3000,1135 3140,1140 3060,1145 3095,1205 2795,1245 3025,1265 3110,1265 2940,1340 2570,1350 2880,1385 2835,1395 2550,1420 2965,1425 2920,1435 2990,1500 3030,1500 3075,1500 2990,1535 3030,1535 3075,1535 2990,1570 3030,1570 3075,1570 2925,1760 3165,1775 2990,1815
HSD0_N: U3.56 USB3.A7 USB3.B7 | length 1468
  Top Layer 1 w7.74: v1(142.19,1663.26) 142.19,1661.09 149.05,1654.23 149.05,1645.08 149.13,1645 149.13,1576.45 163,1562.58 163,1476.6 163.26,1476.34 163.26,1472.11 324.83,1310.54 329.46,1310.54 335,1305 593.03,1305 610.03,1288 988.09,1288 994.11,1294.02 1010.93,1294.02 1015.47,1289.48 1015.47,1283.01 1014.7,1282.25 U3.56@1014.7,1270.4 ; USB3.A7@359.32,1675.15 359.39,1675.08 384.92,1675.08 v1(385,1675)
  Layer2 w7.74: USB3.B7@307.14,1700.75 332.89,1675 v1(385,1675)
  Bottom Layer 1 w7.74: v1(142.19,1663.26) 142.19,1664.6 149.39,1671.8 149.39,1690.61 161.06,1702.28 219.98,1702.28 231.26,1691 294.67,1691 304.42,1700.75 USB3.B7@307.14,1700.75
HSD0_P: U3.55 USB3.A6 USB3.B6 | length 1522.3
  Top Layer 1 w7.74: v1(165,1665) 165,1662.83 161.05,1658.88 161.05,1581.13 174.74,1567.44 174.74,1500.26 175,1500 175,1476.97 179.72,1472.26 184.25,1467.72 190.66,1467.72 195.55,1472.61 200.57,1472.61 208.1,1465.09 208.1,1460.07 203.2,1455.18 203.2,1448.77 218.49,1433.49 320,1331.97 329.69,1322.28 336.1,1322.28 340.64,1326.81 340.64,1328.45 344.18,1332 354.83,1332 358.38,1328.45 358.38,1320.29 361.92,1316.74 372.57,1316.74 376.12,1320.29 376.12,1328.45 379.66,1332 390.31,1332 393.86,1328.45 393.86,1321.53 398.39,1317 420,1317 598,1317 615,1300 983.12,1300 989.14,1306.02 1015.9,1306.02 1027.47,1294.45 1027.47,1285.28 1030.5,1282.25 U3.55@1030.5,1270.4 ; USB3.B6@311.44,1669.25 USB3.B6@307.15,1669.25 331.2,1693.3 357.77,1693.3 USB3.A6@359.32,1694.85 360.86,1693.3 383.14,1693.3 384,1692.44
  Bottom Layer 1 w7.74: v1@161.13,1671.04 161.13,1685.74 165.66,1690.28 180,1690.28 201.61,1690.28 206.14,1685.74 206.14,1667.54 209.69,1664 220.34,1664 223.88,1667.54 223.88,1675.71 227.43,1679.26 238.08,1679.26 241.62,1675.71 241.62,1667.91 245.17,1664.36 255.82,1664.36 259.36,1667.91 259.36,1674.46 263.9,1679 270,1679 294.67,1679 304.42,1669.25 USB3.B6@307.15,1669.25
HSD1_N: U3.10 USB1.2 | length 1151.1
  Top Layer 1 w7.74: USB1.2@330.63,551.82 364,518.45 364,489.51 400.51,453 483,453 627.5,597.5 627.5,697.5 728,798 1071.82,798 1138.85,865.03 1138.85,906.3 1140.7,908.15 U3.10@1140.7,920
HSD1_P: U3.9 USB1.3 | length 1148.6
  Top Layer 1 w7.74: USB1.3@409.37,551.82 376,518.44 376,494.48 405.48,465 460,465 478.03,465 489.78,476.75 489.78,483.16 486.23,486.71 486.23,491.73 493.76,499.25 498.77,499.25 502.32,495.7 508.73,495.7 524.01,510.99 615.5,602.47 615.5,620 615.5,626.58 610.97,631.12 604.05,631.12 600.5,634.66 600.5,645.31 604.05,648.86 610.97,648.86 615.5,653.39 615.5,675 615.5,702.47 723.03,810 1066.85,810 1126.85,870 1126.85,906.3 1125,908.15 U3.9@1125,920
HSD2_N: U3.19 USB4.2 | length 756.2
  Top Layer 1 w7.74: USB4.2@1015.63,546.82 1049,513.45 1049,469.03 1072.13,445.9 1192.87,445.9 1278.7,531.73 1278.7,904.45 1282.4,908.15 U3.19@1282.4,920
HSD2_P: U3.18 USB4.3 | length 753.6
  Top Layer 1 w7.74: USB4.3@1094.37,546.81 1061,513.44 1061,474 1077.1,457.9 1100,457.9 1104.53,457.9 1109.85,463.23 1109.85,464.11 1115.17,469.43 1122.27,469.43 1127.59,464.11 1127.59,462.97 1132.91,457.64 1140.01,457.64 1145.33,462.97 1145.33,472.58 1150.65,477.9 1157.75,477.9 1163.07,472.58 1163.07,463.23 1168.39,457.9 1187.9,457.9 1190,460 1266.7,536.7 U3.18@1266.7,920
HSD3_N: U3.23 USB2.2 | length 876.6
  Top Layer 1 w7.74: U3.23@1315.9,1000.7 1327.75,1000.7 1329.6,998.85 1344.49,998.85 1390,953.34 1390,735 1390,731.13 1394.53,726.6 1399.7,726.6 1403.24,723.05 1403.24,712.4 1399.7,708.86 1394.53,708.86 1390,704.32 1390,690 1390,680.18 1488.25,581.93 1488.44,581.93 1495.47,574.9 1495.47,511.5 1524.97,482 1595.55,482 1666.14,482 1675,490.86 1697.03,512.89 1697.03,519.31 USB2.2@1663.66,552.68
HSD3_P: U3.22 USB2.3 | length 879.4
  Top Layer 1 w7.74: U3.22@1315.9,985 1327.75,985 1329.6,986.85 1339.52,986.85 1378,948.37 1378,675.21 1483.28,569.93 1483.47,569.93 1483.47,506.53 1520,470 1671.11,470 1709.03,507.92 1709.03,519.31 USB2.3@1742.4,552.68
HSD4_N: U3.38 U10.6 | length 571.2
  Top Layer 1 w7.74: U3.38@1315.9,1236.9 1327.75,1236.9 1329.6,1235.05 1435.05,1235.05 1693.14,1493.14 1736.17,1493.14 1746.84,1503.81 U10.6@1775,1503.81
HSD4_P: U3.37 U10.7 | length 568
  Top Layer 1 w7.74: U3.37@1315.9,1221.2 1327.75,1221.2 1329.6,1223.05 1440.02,1223.05 1698.11,1481.14 1736.33,1481.14 1737.99,1479.48 1773.74,1479.48 U10.7@1775,1478.22
INX_N: U9.1 U10.1 | length 1078.1
  Top Layer 1 w6.7: U10.1@1775,1631.77 1746.77,1631.77 1735.7,1642.84 1735.7,1674.73 1739.62,1678.65 1755,1678.65 1775.05,1678.65 cw(c1775.05,1670.3) 1783.4,1670.3 1783.4,1667 ccw(c1791.75,1667) 1800.1,1667 1800.1,1670.3 cw(c1808.45,1670.3) 1808.45,1678.65 1830,1678.65 1848.25,1678.65 1861.9,1665 1869.3,1657.6 1869.3,1649.12 cw(c1860.95,1649.12) 1860.95,1640.77 1857.65,1640.77 ccw(c1857.65,1632.42) 1857.65,1624.07 1860.95,1624.07 cw(c1860.95,1615.72) 1869.3,1615.72 1869.3,1580 1869.3,1455.7 2000,1325 2152.89,1325 2171.44,1343.56 2239.22,1411.33 2244.77,1411.33 2246.26,1409.84 2250.98,1409.84 2258.07,1416.92 2258.07,1421.64 2256.58,1423.14 2256.58,1428.69 2258.94,1431.06 2281.59,1453.7 2309.14,1453.7 2313.06,1449.78 2313.06,1439.2 2303.31,1429.45 U9.1@2303.31,1411.73
INX_P: U9.2 U10.2 | length 1082.8
  Top Layer 1 w6.7: U10.2@1775,1606.18 1749.94,1606.18 1746.41,1609.7 1746.41,1612.7 1725,1634.12 1725,1679.16 1735.19,1689.35 1852.68,1689.35 1880,1662.03 1880,1580 1880,1460.13 2004.43,1335.7 2146.62,1335.7 2276.62,1465.7 2314.11,1465.7 2325.06,1454.75 2325.06,1439.2 2334.81,1429.45 U9.2@2334.81,1411.73
ISO+3.3V: C59.2 C90.2 C91.2 R31.1 R32.1 U8.5 U11.16 U15.21 | length 1624.4
  Top Layer 1 w10: C90.2@2954.57,1650 2954.57,1648.03 2980.09,1622.52 2981.7,1622.52 2982.76,1621.46 U15.21@2982.76,1613.74
  Top Layer 1 w15: U11.16@2650,1163.82 2750,1163.82
  Top Layer 1 w35: 2750,1163.82 2750,1500 2900,1650 ; C90.2@2954.57,1650 2925,1650 2900,1650 ; U8.5@3105.42,1852.4 3185.1,1852.4 3187.5,1850 3202.5,1850 3241.5,1811 3241.5,1748.79 3217.71,1725 v1(3170,1725) 2975,1725 2900,1650
  Bottom Layer 1 w10: R31.1@3105,1500.43 3106.14,1501.57 3143.86,1501.57 R32.1@3145,1502.72 3146.97,1502.72 3170,1525.75 v1(3170,1725)
  other v2: 2730,1145
ISO+5V: C58.2 U8.1 U8.3 U12.6 USB5.1 | length 1688
  Top Layer 1 w25: U8.3@3024.9,1777.6 3050.36,1777.6 3065,1792.24 3065,1837.76 3050.36,1852.4 U8.1@3024.9,1852.4
  Layer2 w45: U12.6@2645,1890 2645,1883 2615,1853 2615,1485 2935,1165 2935,654.57 3052.2,537.36 USB5.1@3052.2,533.34
LED0: RJ1.13 U6.32 | length 1341.3
  Top Layer 1 w10: U6.32@1828.82,1040.85 1827.07,1039.1 1827.07,1032.12 1770,975.06 1770,840 2034,576 2034,446 2180,300 2499.38,300 RJ1.13@2560.83,238.54
LED1: RJ1.12 U6.30 | length 1085.9
  Top Layer 1 w10: U6.30@1786.6,1079.13 1786.6,1019.72 1745,978.12 1745,825 2005,565 2005,432.77 2166.77,271 2203.09,271 2235.54,238.54 RJ1.12@2239.17,238.54
MDI0_N: RJ1.P3 U6.2 | length 517.9
  Top Layer 1 w6.7: U6.2@1983.4,1094.88 1995.21,1094.88 1999.55,1090.54 2002.68,1090.54 2224.15,869.08 2224.15,754.77 2233.36,745.56 2238.91,745.56 RJ1.P3@2274.8,781.45
MDI0_P: RJ1.P2 U6.1 | length 517.6
  Top Layer 1 w6.7: U6.1@1983.4,1079.13 1983.99,1078.54 1997.71,1078.54 2170.63,905.63 2170.63,894.37 2180,885 2191.26,885 2212.15,864.11 2212.15,749.8 2229.27,732.67 2229.27,689.83 RJ1.P2@2220.9,681.45
MDI1_N: RJ1.P7 U6.5 | length 898.4
  Top Layer 1 w6.7: U6.5@1983.4,1142.13 1995.21,1142.13 1998.39,1138.95 2057.1,1138.95 2328.7,867.35 2329.35,866.7 2329.35,771.7 2374.35,726.7 2374.35,675.18 2405.43,644.11 2436.37,644.11 2474.8,682.53 RJ1.P7@2474.8,781.45
MDI1_P: RJ1.P4 U6.4 | length 902.6
  Top Layer 1 w6.7: U6.4@1983.4,1126.38 1995.21,1126.38 1997.09,1128.26 2052.66,1128.26 2318,862.92 2318.65,862.27 2318.65,767.27 2363.65,722.27 2363.65,670.75 2399.7,634.7 2399.7,609.7 2380,590 2334.82,590 2320.9,603.92 RJ1.P4@2320.9,681.45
